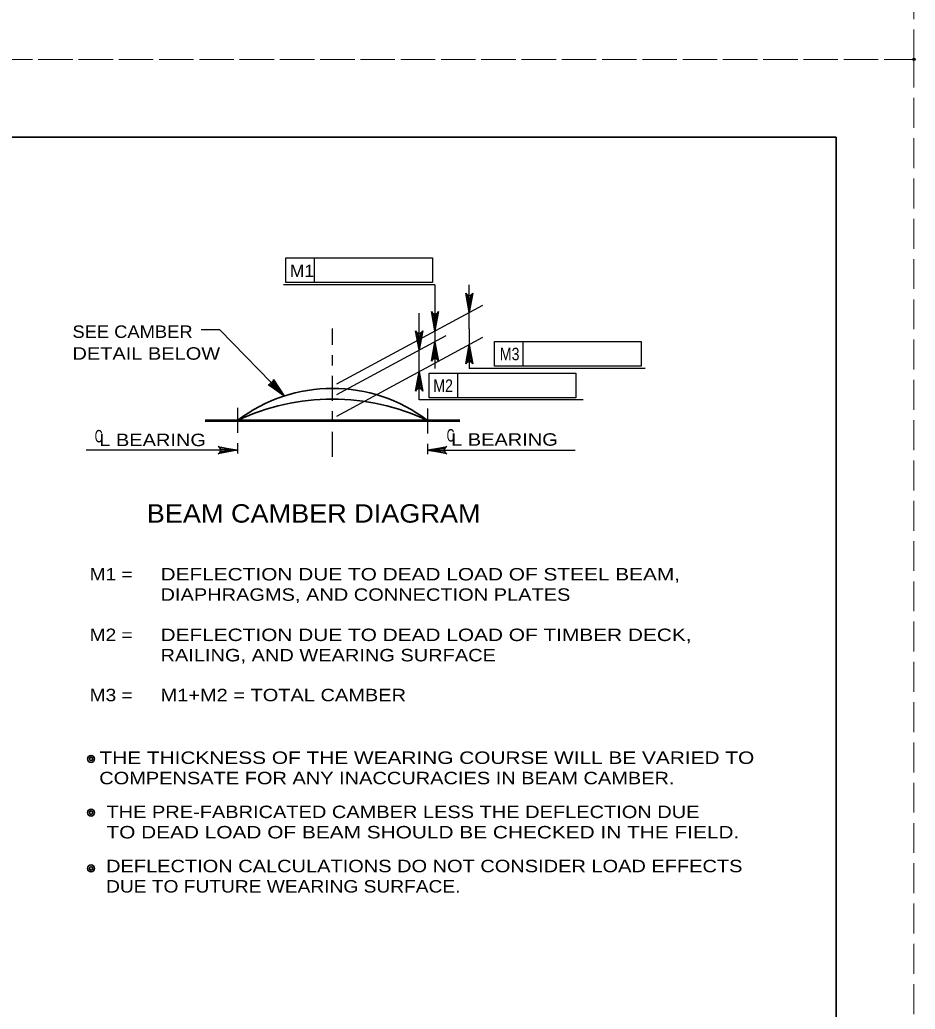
# Model space of a CAD drawing. Extents: x -11 to 79, y -154 to 0.
# Drawn here: x 59.39 to 68.01, y -31.15 to -21.62 of the extents above; entities that cross this region are included whole.
import ezdxf
from ezdxf.enums import TextEntityAlignment as Align

# ---------------------------------------------------------------- set-up
doc = ezdxf.new("R2010")
doc.units = 0
doc.header["$LTSCALE"] = 0.048
doc.header["$PDMODE"] = 32
doc.header["$PDSIZE"] = 0.024
doc.linetypes.add('DOT_DASHED', pattern=[7.7, 5, -1.2, 0.3, -1.2])
doc.linetypes.add('LONG_DASHED', pattern=[7.5, 6, -1.5])
for name, color, linetype, lineweight in [('1', 7, 'Continuous', 25), ('3', 7, 'Continuous', 25), ('5', 7, 'Continuous', 25), ('6', 7, 'Continuous', 25), ('63', 7, 'LONG_DASHED', 13)]:
    doc.layers.add(name, color=color, linetype=linetype, lineweight=lineweight)
doc.layers.add('62', color=7, linetype='Continuous')

msp = doc.modelspace()

# ---------------------------------------------------------------- hatches: boundary and pattern name
at = {"layer": '3'}
for points in [[(63.73608, -24.31933), (63.69675, -24.31933), (63.71642, -24.43742)], [(63.40542, -24.498), (63.366, -24.498), (63.38575, -24.61608)], [(63.25342, -24.68342), (63.21408, -24.68342), (63.23375, -24.8015)], [(63.366, -24.8375), (63.40542, -24.8375), (63.38575, -24.71942)], [(63.69675, -24.86558), (63.73608, -24.86558), (63.71642, -24.74742)], [(63.21408, -25.12633), (63.25342, -25.12633), (63.23375, -25.00825)], [(61.8295, -25.09283), (61.78658, -25.13475), (61.93383, -25.2425)], [(61.36492, -25.78425), (61.36492, -25.74483), (61.48308, -25.7645)], [(63.43183, -25.78425), (63.43183, -25.74483), (63.31375, -25.7645)]]:
    msp.add_hatch(color=256, dxfattribs=at).paths.add_polyline_path(points)

# ---------------------------------------------------------------- linework, layer by layer
at = {"layer": '1', "lineweight": 35}
msp.add_lwpolyline([(35.75, -43.25), (67.25, -43.25), (67.25, -22.75), (35.75, -22.75)], close=True, dxfattribs=at)
at = {"layer": '3'}
for p, q in [((61.94833, -23.91275), (63.36033, -23.91275)), ((61.94833, -24.14892), (61.94833, -23.91275)), ((62.22392, -24.14892), (62.22392, -23.91275)), ((63.36033, -23.91275), (63.36033, -24.14892)), ((63.38575, -24.17233), (61.92617, -24.17233)), ((63.36033, -24.14892), (61.94833, -24.14892)), ((63.38575, -24.17233), (63.38575, -24.97692)), ((63.71642, -24.59642), (63.71642, -24.17233)), ((62.441, -25.12642), (63.848, -24.36633)), ((63.23375, -25.28075), (63.23375, -24.44342)), ((62.441, -25.22983), (63.49417, -24.66083)), ((62.441, -25.4365), (63.848, -24.67633)), ((63.71642, -24.59642), (63.71642, -24.97692)), ((63.95892, -24.71908), (65.371, -24.71908)), ((64.2345, -24.95525), (64.2345, -24.71908)), ((65.371, -24.71908), (65.371, -24.95525)), ((63.32975, -25.02383), (64.74175, -25.02383)), ((63.32975, -25.26), (63.32975, -25.02383)), ((63.60533, -25.26), (63.60533, -25.02383)), ((65.41133, -24.97692), (63.71642, -24.97692)), ((64.74175, -25.02383), (64.74175, -25.26)), ((64.81392, -25.28075), (63.23375, -25.28075)), ((64.74175, -25.26), (63.32975, -25.26)), ((61.48308, -25.7645), (60.024, -25.7645)), ((63.31375, -25.7645), (64.736, -25.7645))]:
    msp.add_line(p, q, dxfattribs=at)
at = {"layer": '3', "linetype": 'DOT_DASHED'}
for p, q in [((62.39842, -25.82883), (62.39842, -24.59092)), ((61.48308, -25.35725), (61.48308, -25.83417)), ((63.31375, -25.36258), (63.31375, -25.83958))]:
    msp.add_line(p, q, dxfattribs=at)
at = {"layer": '3'}
for points in [[(63.71642, -24.43742), (63.6815, -24.251), (63.69142, -24.26533), (63.70392, -24.27275), (63.71642, -24.27492), (63.72892, -24.27275), (63.74142, -24.26533), (63.75133, -24.251), (63.71642, -24.43742), (63.74142, -24.26533), (63.72892, -24.27275), (63.71642, -24.43742), (63.71642, -24.27492), (63.70392, -24.27275), (63.71642, -24.43742), (63.69142, -24.26533)], [(63.38575, -24.61608), (63.35083, -24.42967), (63.36075, -24.444), (63.37325, -24.45142), (63.38575, -24.45358), (63.39825, -24.45142), (63.41075, -24.444), (63.42067, -24.42967), (63.38575, -24.61608), (63.41075, -24.444), (63.39825, -24.45142), (63.38575, -24.61608), (63.38575, -24.45358), (63.37325, -24.45142), (63.38575, -24.61608), (63.36075, -24.444)], [(61.93383, -25.2425), (61.31183, -24.606), (61.13183, -24.606)], [(63.23375, -24.8015), (63.19883, -24.61508), (63.20875, -24.62942), (63.22125, -24.63683), (63.23375, -24.639), (63.24625, -24.63683), (63.25875, -24.62942), (63.26867, -24.61508), (63.23375, -24.8015), (63.25875, -24.62942), (63.24625, -24.63683), (63.23375, -24.8015), (63.23375, -24.639), (63.22125, -24.63683), (63.23375, -24.8015), (63.20875, -24.62942)], [(63.38575, -24.71942), (63.42067, -24.90583), (63.41075, -24.8915), (63.39825, -24.88408), (63.38575, -24.88192), (63.37325, -24.88408), (63.36075, -24.8915), (63.35083, -24.90583), (63.38575, -24.71942), (63.36075, -24.8915), (63.37325, -24.88408), (63.38575, -24.71942), (63.38575, -24.88192), (63.39825, -24.88408), (63.38575, -24.71942), (63.41075, -24.8915)], [(63.71642, -24.74742), (63.75133, -24.93383), (63.74142, -24.9195), (63.72892, -24.91208), (63.71642, -24.90992), (63.70392, -24.91208), (63.69142, -24.9195), (63.6815, -24.93383), (63.71642, -24.74742), (63.69142, -24.9195), (63.70392, -24.91208), (63.71642, -24.74742), (63.71642, -24.90992), (63.72892, -24.91208), (63.71642, -24.74742), (63.74142, -24.9195)], [(65.371, -24.95525), (63.95892, -24.95525), (63.95892, -24.71908)], [(63.23375, -25.00825), (63.26867, -25.19467), (63.25875, -25.18033), (63.24625, -25.17292), (63.23375, -25.17075), (63.22125, -25.17292), (63.20875, -25.18033), (63.19883, -25.19467), (63.23375, -25.00825), (63.20875, -25.18033), (63.22125, -25.17292), (63.23375, -25.00825), (63.23375, -25.17075), (63.24625, -25.17292), (63.23375, -25.00825), (63.25875, -25.18033)], [(61.93383, -25.2425), (61.77858, -25.13358), (61.79567, -25.13692), (61.80983, -25.1335), (61.82025, -25.12625), (61.82767, -25.116), (61.8315, -25.102), (61.82858, -25.08475), (61.93383, -25.2425), (61.8315, -25.102), (61.82767, -25.116), (61.93383, -25.2425), (61.82025, -25.12625), (61.80983, -25.1335), (61.93383, -25.2425), (61.79567, -25.13692)], [(61.48308, -25.7645), (61.29667, -25.79942), (61.311, -25.7895), (61.31842, -25.777), (61.32058, -25.7645), (61.31842, -25.752), (61.311, -25.7395), (61.29667, -25.72958), (61.48308, -25.7645), (61.311, -25.7395), (61.31842, -25.752), (61.48308, -25.7645), (61.32058, -25.7645), (61.31842, -25.777), (61.48308, -25.7645), (61.311, -25.7895)], [(63.31375, -25.7645), (63.50017, -25.72958), (63.48583, -25.7395), (63.47842, -25.752), (63.47625, -25.7645), (63.47842, -25.777), (63.48583, -25.7895), (63.50017, -25.79942), (63.31375, -25.7645), (63.48583, -25.7895), (63.47842, -25.777), (63.31375, -25.7645), (63.47625, -25.7645), (63.47842, -25.752), (63.31375, -25.7645), (63.48583, -25.7395)]]:
    msp.add_lwpolyline(points, dxfattribs=at)
for points in [[(63.73608, -24.31933), (63.69675, -24.31933), (63.71642, -24.43742)], [(63.40542, -24.498), (63.366, -24.498), (63.38575, -24.61608)], [(63.25342, -24.68342), (63.21408, -24.68342), (63.23375, -24.8015)], [(63.366, -24.8375), (63.40542, -24.8375), (63.38575, -24.71942)], [(63.69675, -24.86558), (63.73608, -24.86558), (63.71642, -24.74742)], [(63.21408, -25.12633), (63.25342, -25.12633), (63.23375, -25.00825)], [(61.8295, -25.09283), (61.78658, -25.13475), (61.93383, -25.2425)], [(61.36492, -25.78425), (61.36492, -25.74483), (61.48308, -25.7645)], [(63.43183, -25.78425), (63.43183, -25.74483), (63.31375, -25.7645)]]:
    msp.add_lwpolyline(points, close=True, dxfattribs=at)
at = {"layer": '3', "lineweight": 35}
for centre, radius in [((60.07247, -28.73845), 0.03333), ((60.07247, -28.73845), 0.01667), ((60.07247, -29.2557), 0.03333), ((60.07247, -29.2557), 0.01667), ((60.07247, -29.79284), 0.03333), ((60.07247, -29.79284), 0.01667)]:
    msp.add_circle(centre, radius, dxfattribs=at)
at = {"layer": '5', "lineweight": 35}
for centre, radius, start, end in [((62.39837, -26.67534), 1.50625, 52.57652, 127.42348), ((62.39837, -27.40263), 2.1302, 64.55129, 115.44871)]:
    msp.add_arc(centre, radius, start, end, dxfattribs=at)
at = {"layer": '6', "lineweight": 53}
msp.add_line((61.17225, -25.47908), (63.62458, -25.47908), dxfattribs=at)
at = {"layer": '62'}
msp.add_point((68, -22), dxfattribs=at)
at = {"layer": '63'}
for points in [[(34, -22), (68, -22), (68, 0), (34, 0)], [(34, -44), (68, -44), (68, -22), (34, -22)]]:
    msp.add_lwpolyline(points, close=True, dxfattribs=at)

# ---------------------------------------------------------------- texts
at = {"layer": '3'}
for s, height, width, p in [('M1', 0.12, 1.05, (62.10404, -24.09717)), ('M3', 0.12, 0.85, (64.10504, -24.89808)), ('M2', 0.12, 0.85, (63.46412, -25.20283)), ('BEAM CAMBER DIAGRAM', 0.1772, 1.1, (62.21692, -26.46233))]:
    msp.add_text(s, height=height, dxfattribs=dict(at, width=width)).set_placement(p, align=Align.CENTER)
for s, width, p in [('SEE CAMBER', 1.1, (59.89308, -24.68308)), ('DETAIL BELOW', 1.2, (59.89308, -24.89308)), ('C', 0.65, (60.10792, -25.68942)), ('L BEARING', 1.2, (60.15183, -25.7255)), ('C', 0.65, (63.49825, -25.68167)), ('L BEARING', 1.2, (63.54108, -25.72167)), ('M1 =', 1.15, (60.05833, -27.0195)), ('DEFLECTION DUE TO DEAD LOAD OF STEEL BEAM,', 1.25, (60.74175, -27.0195)), ('DIAPHRAGMS, AND CONNECTION PLATES', 1.2, (60.74175, -27.21525)), ('M2 =', 1.15, (60.05833, -27.60308)), ('DEFLECTION DUE TO DEAD LOAD OF TIMBER DECK,', 1.25, (60.74175, -27.60308)), ('RAILING, AND WEARING SURFACE', 1.2, (60.74175, -27.79892)), ('M3 =', 1.15, (60.05833, -28.18283)), ('M1+M2 = TOTAL CAMBER', 1.2, (60.74175, -28.18283)), (' THE THICKNESS OF THE WEARING COURSE WILL BE VARIED TO', 1.25, (60.0975, -28.78667)), (' COMPENSATE FOR ANY INACCURACIES IN BEAM CAMBER.', 1.2, (60.0975, -28.9825)), ('THE PRE-FABRICATED CAMBER LESS THE DEFLECTION DUE', 1.2, (60.22058, -29.30825)), ('TO DEAD LOAD OF BEAM SHOULD BE CHECKED IN THE FIELD.', 1.25, (60.22058, -29.50408)), ('DEFLECTION CALCULATIONS DO NOT CONSIDER LOAD EFFECTS', 1.2, (60.21717, -29.82975)), ('DUE TO FUTURE WEARING SURFACE.', 1.15, (60.21717, -30.02558))]:
    msp.add_text(s, height=0.12, dxfattribs=dict(at, width=width)).set_placement(p)

doc.saveas('drawing.dxf')
